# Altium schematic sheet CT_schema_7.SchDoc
size 287 x 160 mm
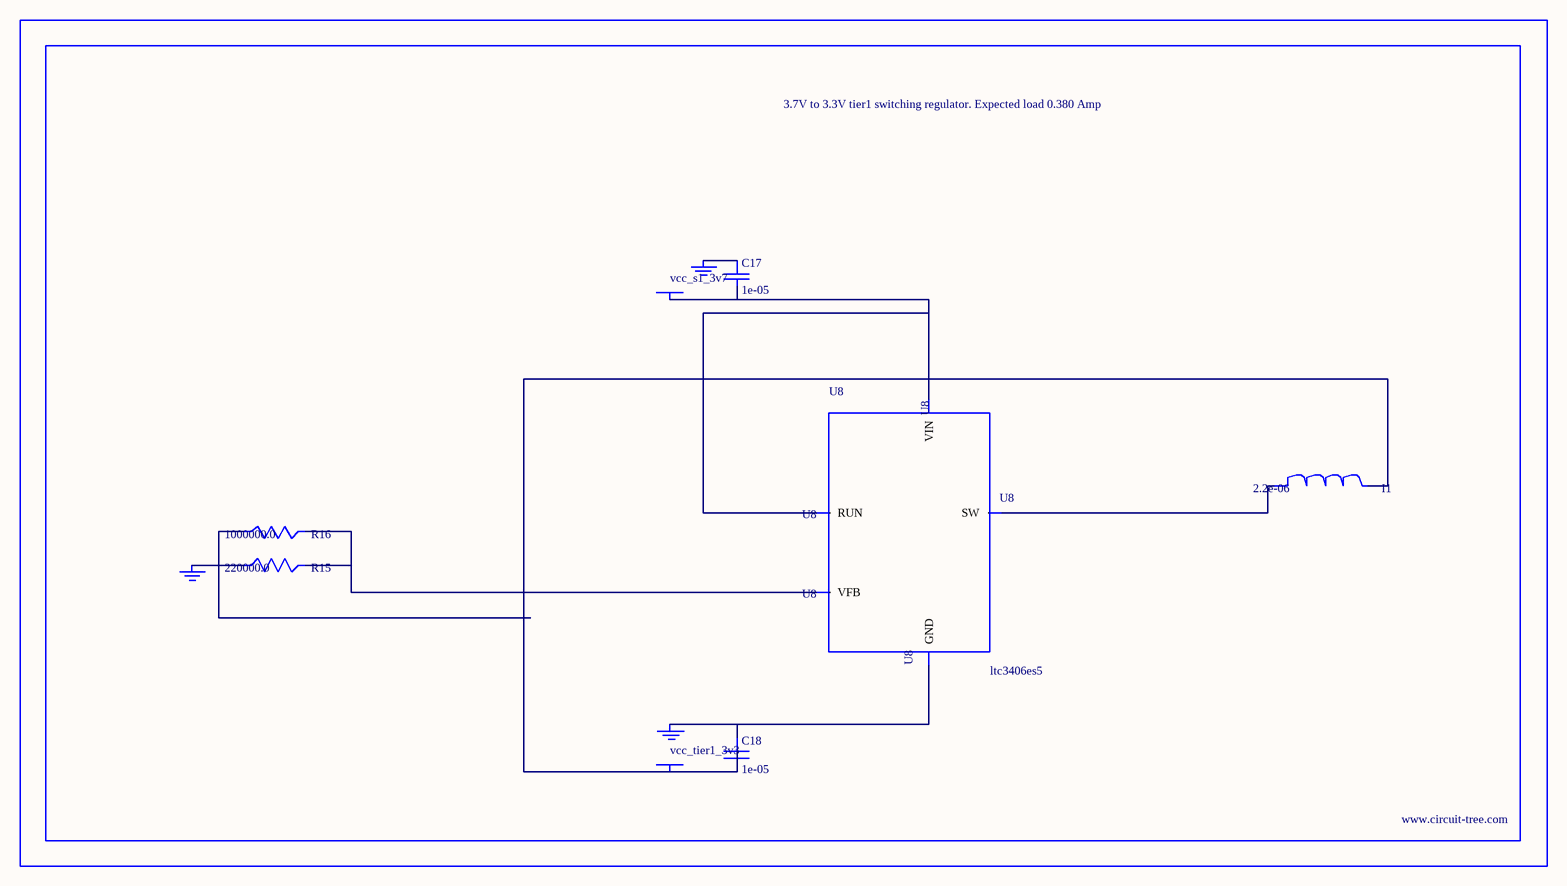
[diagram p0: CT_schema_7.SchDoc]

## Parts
BORDER6  (no value)
C17  1e-05  [C0805]
C18  1e-05  [C0805]
GND_INSTANCE_6_0  (no value)
GND_INSTANCE_6_1  (no value)
GND_INSTANCE_6_2  (no value)
I1  2.2e-06  [L0805]
POWER_INSTANCE_6_0  vcc_tier1_3v3
POWER_INSTANCE_6_1  vcc_s1_3v7
R15  220000.0  [R0603]
R16  1000000.0  [R0603]
U8  ltc3406es5  [TSOT-23-5]

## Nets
NetC17_1: C17.1 GND_INSTANCE_6_1.0(GND)
NetC17_2: C17.2 POWER_INSTANCE_6_1.0(PWR) U8.1(RUN) U8.4(VIN)
NetC18_1: C18.1 GND_INSTANCE_6_0.0(GND) U8.2(GND)
NetC18_2: C18.2 I1.2 POWER_INSTANCE_6_0.0(PWR) R16.1
NetGND_INSTANCE_6_2_0: GND_INSTANCE_6_2.0(GND) R15.1
NetI1_1: I1.1 U8.3(SW)
NetR15_2: R15.2 R16.2 U8.5(VFB)

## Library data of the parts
BORDER6 = BORDER_PAGE6
C17 C18 = C0805C106K8RACTU
GND_INSTANCE_6_0-GND_INSTANCE_6_2 = GND
I1 = L0805C2R2MDWIT
POWER_INSTANCE_6_0 POWER_INSTANCE_6_1 = PWR
R15 = RC0603JR-07220KL
R16 = RC0603JR-071ML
